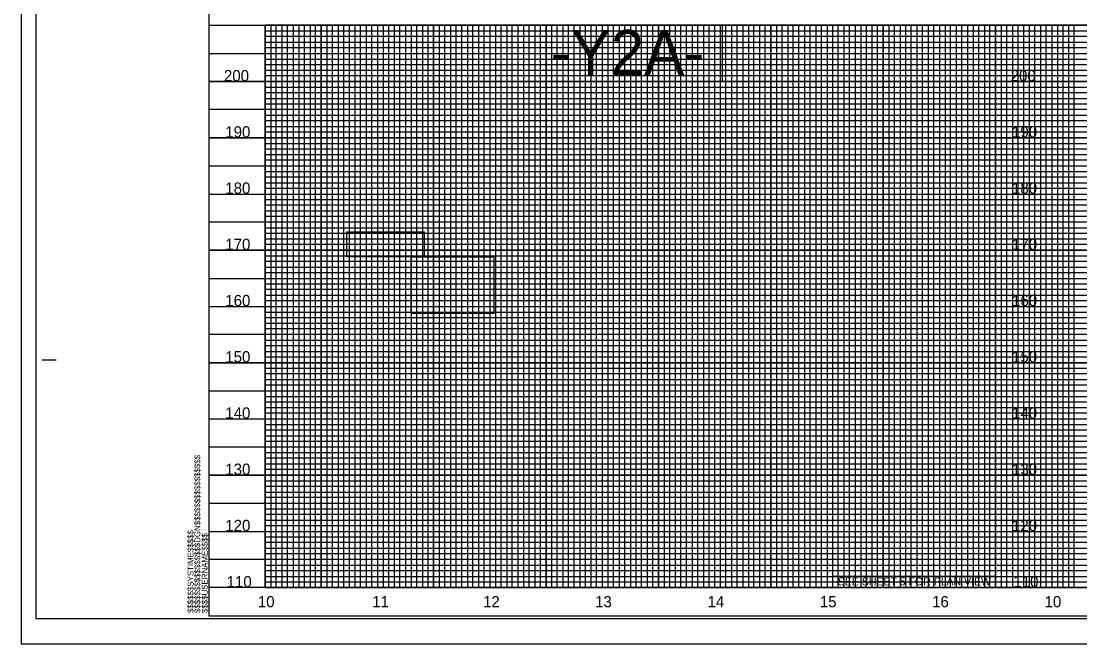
# Model space of a CAD drawing. Extents: x 1779926 to 1781626, y 618464 to 619564.
# Drawn here: x 1779926 to 1780868, y 618464 to 619018 of the extents above; entities that cross this region are included whole.
import ezdxf

# ---------------------------------------------------------------- set-up
doc = ezdxf.new("R2010")
doc.units = 0
for name, color, linetype in [('Exist Vertical Profile Horizontal Axis Label Major', 7, 'Continuous'), ('Exist Vertical Profile Vertical Axis Label', 7, 'Continuous'), ('Prop DSN Text', 7, 'Continuous'), ('Prop Grid Mask', 7, 'Continuous'), ('Sheet DOT Grid CELL', 7, 'Continuous'), ('Sheet Layout Profile Border Port 2', 7, 'Continuous'), ('Sheet Plot Border Inside CELL', 7, 'Continuous'), ('Sheet Plot Border Outside CELL', 7, 'Continuous'), ('Sheet Profile CELL', 7, 'Continuous'), ('Sheet Profile Grid Major CELL', 7, 'Continuous'), ('Sheet Profile Grid Middle CELL', 7, 'Continuous'), ('Sheet Profile Grid Minor CELL', 7, 'Continuous')]:
    doc.layers.add(name, color=color, linetype=linetype)

msp = doc.modelspace()

# ---------------------------------------------------------------- linework, layer by layer
at = {"layer": 'Prop Grid Mask'}
for points in [[(1780550.05, 619014.19), (1780393.09, 619014.19), (1780393.09, 618964.19), (1780550.05, 618964.19)], [(1780792.96, 619014.19), (1780842.96, 619014.19), (1780842.96, 618514.19), (1780792.96, 618514.19)], [(1780215.65, 618830.56), (1780284.61, 618830.56), (1780284.61, 618808.4), (1780215.65, 618808.4)], [(1780272.96, 618808.4), (1780346.37, 618808.4), (1780346.37, 618758.05), (1780272.96, 618758.05)], [(1780792.96, 618524.19), (1780647.96, 618524.19), (1780647.96, 618514.19), (1780792.96, 618514.19)]]:
    msp.add_lwpolyline(points, close=True, dxfattribs=at)
at = {"layer": 'Sheet DOT Grid CELL'}
for p, q in [((1780092.96, 619014.19), (1781592.85, 619014.19)), ((1780142.96, 619014.19), (1780142.96, 618514.19)), ((1780192.96, 619014.19), (1780192.96, 618514.19)), ((1780242.96, 619014.19), (1780242.96, 618514.19)), ((1780292.96, 619014.19), (1780292.96, 618514.19)), ((1780342.96, 619014.19), (1780342.96, 618514.19)), ((1780392.96, 619014.19), (1780392.96, 618514.19)), ((1780442.96, 619014.19), (1780442.96, 618514.19)), ((1780492.96, 619014.19), (1780492.96, 618514.19)), ((1780542.96, 619014.19), (1780542.96, 618514.19)), ((1780592.96, 619014.19), (1780592.96, 618514.19)), ((1780642.96, 619014.19), (1780642.96, 618514.19)), ((1780692.96, 619014.19), (1780692.96, 618514.19)), ((1780742.96, 619014.19), (1780742.96, 618514.19)), ((1780792.96, 619014.19), (1780792.96, 618514.19)), ((1780842.96, 619014.19), (1780842.96, 618514.19)), ((1780092.96, 618964.19), (1781592.85, 618964.19)), ((1780092.96, 618914.19), (1781592.85, 618914.19)), ((1780092.96, 618864.19), (1781592.85, 618864.19)), ((1780092.96, 618814.19), (1781592.85, 618814.19)), ((1780092.96, 618764.19), (1781592.85, 618764.19)), ((1780092.96, 618714.19), (1781592.85, 618714.19)), ((1780092.96, 618664.19), (1781592.85, 618664.19)), ((1780092.96, 618614.19), (1781592.85, 618614.19)), ((1780092.96, 618564.19), (1781592.85, 618564.19))]:
    msp.add_line(p, q, dxfattribs=at)
at = {"layer": 'Sheet Layout Profile Border Port 2'}
msp.add_lwpolyline([(1780142.96, 619014.19), (1781542.96, 619014.19), (1781542.96, 618514.19), (1780142.96, 618514.19)], close=True, dxfattribs=at)
msp.add_lwpolyline([(1781442.96, 619014.19), (1780142.96, 619014.19), (1780142.96, 618514.19), (1781542.96, 618514.19), (1781542.96, 619014.19)], dxfattribs=at)
at = {"layer": 'Sheet Plot Border Inside CELL'}
msp.add_lwpolyline([(1779938.96, 618486.64), (1781605.46, 618486.64), (1781605.46, 619541.74), (1779938.96, 619541.74)], close=True, dxfattribs=at)
at = {"layer": 'Sheet Plot Border Outside CELL'}
msp.add_lwpolyline([(1779925.96, 618464.19), (1781625.96, 618464.19), (1781625.96, 619564.19), (1779925.96, 619564.19)], close=True, dxfattribs=at)
at = {"layer": 'Sheet Profile CELL'}
for p, q in [((1780092.96, 619014.19), (1781592.96, 619014.19)), ((1779944.46, 618716.69), (1779956.96, 618716.69)), ((1781592.96, 618514.19), (1780092.96, 618514.19)), ((1780092.96, 618489.19), (1781592.96, 618489.19)), ((1780092.96, 618489.19), (1780092.96, 618489.19)), ((1780092.96, 618489.19), (1780092.96, 618489.19)), ((1780092.96, 618489.19), (1780092.96, 618489.19)), ((1780092.96, 618489.19), (1780092.96, 618489.19)), ((1780092.96, 618489.19), (1780092.96, 618489.19)), ((1780092.96, 618489.19), (1780092.96, 618489.19)), ((1780092.96, 618489.19), (1780092.96, 618489.19))]:
    msp.add_line(p, q, dxfattribs=at)
msp.add_lwpolyline([(1781592.96, 619539.19), (1780092.96, 619539.19), (1780092.96, 618489.19), (1781592.96, 618489.19)], close=True, dxfattribs=at)
msp.add_lwpolyline([(1780130.46, 618489.19), (1780130.46, 618489.19)], dxfattribs=at)
at = {"layer": 'Sheet Profile Grid Major CELL'}
for p, q in [((1780592.96, 619014.19), (1780642.96, 619014.19)), ((1780692.96, 619014.19), (1780742.96, 619014.19)), ((1780792.96, 619014.19), (1780842.96, 619014.19)), ((1780092.96, 618514.19), (1780092.96, 618514.19))]:
    msp.add_line(p, q, dxfattribs=at)
for points in [[(1780142.96, 619014.19), (1780142.96, 618514.19), (1780192.96, 618514.19), (1780192.96, 619014.19), (1780242.96, 619014.19), (1780242.96, 618514.19), (1780292.96, 618514.19), (1780292.96, 619014.19), (1780342.96, 619014.19), (1780342.96, 618514.19), (1780392.96, 618514.19), (1780392.96, 619014.19), (1780442.96, 619014.19), (1780442.96, 618514.19), (1780492.96, 618514.19), (1780492.96, 619014.19), (1780542.96, 619014.19), (1780542.96, 618514.19), (1780592.96, 618514.19), (1780592.96, 619014.19), (1780642.96, 619014.19), (1780642.96, 618514.19), (1780692.96, 618514.19), (1780692.96, 619014.19), (1780742.96, 619014.19), (1780742.96, 618514.19), (1780792.96, 618514.19), (1780792.96, 619014.19), (1780842.96, 619014.19), (1780842.96, 618514.19), (1780892.96, 618514.19)], [(1781592.96, 618964.19), (1780092.96, 618964.19)], [(1781592.96, 618914.19), (1780092.96, 618914.19), (1780092.96, 618864.19), (1781592.96, 618864.19)], [(1781592.96, 618814.19), (1780092.96, 618814.19), (1780092.96, 618764.19), (1781592.96, 618764.19)], [(1781592.96, 618714.19), (1780092.96, 618714.19), (1780092.96, 618664.19), (1781592.96, 618664.19)], [(1781592.96, 618614.19), (1780092.96, 618614.19), (1780092.96, 618614.19), (1780092.96, 618564.19), (1781592.96, 618564.19)], [(1781592.96, 618514.19), (1780092.96, 618514.19)]]:
    msp.add_lwpolyline(points, dxfattribs=at)
at = {"layer": 'Sheet Profile Grid Middle CELL'}
for points in [[(1780117.96, 619014.19), (1780167.96, 619014.19), (1780167.96, 618514.19), (1780217.96, 618514.19), (1780217.96, 619014.19), (1780267.96, 619014.19), (1780267.96, 618514.19), (1780317.96, 618514.19), (1780317.96, 619014.19), (1780367.96, 619014.19), (1780367.96, 618514.19), (1780417.96, 618514.19), (1780417.96, 619014.19), (1780467.96, 619014.19), (1780467.96, 618514.19), (1780517.96, 618514.19), (1780517.96, 619014.19), (1780567.96, 619014.19), (1780567.96, 618514.19), (1780617.96, 618514.19), (1780617.96, 619014.19), (1780667.96, 619014.19), (1780667.96, 618514.19), (1780717.96, 618514.19), (1780717.96, 618514.19), (1780717.96, 619014.19), (1780767.96, 619014.19), (1780767.96, 618514.19), (1780817.96, 618514.19), (1780817.96, 619014.19), (1780867.96, 619014.19)], [(1780092.96, 618989.19), (1781592.96, 618989.19)], [(1781592.96, 618939.19), (1780092.96, 618939.19), (1780092.96, 618889.19), (1781592.96, 618889.19)], [(1781592.96, 618839.19), (1780092.96, 618839.19), (1780092.96, 618789.19), (1781592.96, 618789.19)], [(1781592.96, 618739.19), (1780092.96, 618739.19), (1780092.96, 618689.19), (1781592.96, 618689.19)], [(1781592.96, 618639.19), (1780092.96, 618639.19), (1780092.96, 618589.19), (1781592.96, 618589.19)], [(1781592.96, 618539.19), (1780092.96, 618539.19)]]:
    msp.add_lwpolyline(points, dxfattribs=at)
at = {"layer": 'Sheet Profile Grid Minor CELL'}
for p, q in [((1780142.96, 619009.19), (1781542.96, 619009.19)), ((1781542.96, 619004.19), (1780142.96, 619004.19)), ((1780142.96, 618999.19), (1781542.96, 618999.19)), ((1781542.96, 618994.19), (1780142.96, 618994.19)), ((1780142.96, 618984.19), (1781542.96, 618984.19)), ((1781542.96, 618979.19), (1780142.96, 618979.19)), ((1780142.96, 618974.19), (1781542.96, 618974.19)), ((1781542.96, 618969.19), (1780142.96, 618969.19)), ((1780142.96, 618959.19), (1781542.96, 618959.19)), ((1781542.96, 618954.19), (1780142.96, 618954.19)), ((1780142.96, 618949.19), (1781542.96, 618949.19)), ((1781542.96, 618944.19), (1780142.96, 618944.19)), ((1780142.96, 618934.19), (1781542.96, 618934.19)), ((1781542.96, 618929.19), (1780142.96, 618929.19)), ((1780142.96, 618924.19), (1781542.96, 618924.19)), ((1781542.96, 618919.19), (1780142.96, 618919.19)), ((1780142.96, 618909.19), (1781542.96, 618909.19)), ((1781542.96, 618904.19), (1780142.96, 618904.19)), ((1780142.96, 618899.19), (1781542.96, 618899.19)), ((1781542.96, 618894.19), (1780142.96, 618894.19)), ((1780142.96, 618884.19), (1781542.96, 618884.19)), ((1781542.96, 618879.19), (1780142.96, 618879.19)), ((1780142.96, 618874.19), (1781542.96, 618874.19)), ((1781542.96, 618869.19), (1780142.96, 618869.19)), ((1780142.96, 618859.19), (1781542.96, 618859.19)), ((1781542.96, 618854.19), (1780142.96, 618854.19)), ((1780142.96, 618849.19), (1781542.96, 618849.19)), ((1781542.96, 618844.19), (1780142.96, 618844.19)), ((1780142.96, 618834.19), (1781542.96, 618834.19)), ((1781542.96, 618829.19), (1780142.96, 618829.19)), ((1780142.96, 618824.19), (1781542.96, 618824.19)), ((1781542.96, 618819.19), (1780142.96, 618819.34)), ((1780142.96, 618809.19), (1781542.96, 618809.19)), ((1781542.96, 618804.19), (1780142.96, 618804.19)), ((1780142.96, 618799.19), (1781542.96, 618799.19)), ((1781542.96, 618794.19), (1780142.96, 618794.19)), ((1780142.96, 618784.19), (1781542.96, 618784.19)), ((1781542.96, 618779.19), (1780142.96, 618779.19)), ((1780142.96, 618774.19), (1781542.96, 618774.19)), ((1781542.96, 618769.19), (1780142.96, 618769.19)), ((1780142.96, 618759.19), (1781542.96, 618759.19)), ((1781542.96, 618754.19), (1780142.96, 618754.19)), ((1780142.96, 618749.19), (1781542.96, 618749.19)), ((1781542.96, 618744.19), (1780142.96, 618744.19)), ((1780142.96, 618734.19), (1781542.96, 618734.19)), ((1781542.96, 618729.19), (1780142.96, 618729.19)), ((1780142.96, 618724.19), (1781542.96, 618724.19)), ((1781542.96, 618719.19), (1780142.96, 618719.19)), ((1780142.96, 618709.19), (1781542.96, 618709.19)), ((1781542.96, 618704.19), (1780142.96, 618704.19)), ((1780142.96, 618699.19), (1781542.96, 618699.19)), ((1781542.96, 618694.19), (1780142.96, 618694.19)), ((1780142.96, 618684.19), (1781542.96, 618684.19)), ((1781542.96, 618679.19), (1780142.96, 618679.19)), ((1780142.96, 618674.19), (1781542.96, 618674.19)), ((1781542.96, 618669.19), (1780142.96, 618669.19)), ((1780142.96, 618659.19), (1781542.96, 618659.19)), ((1781542.96, 618654.19), (1780142.96, 618654.19)), ((1780142.96, 618649.19), (1781542.96, 618649.19)), ((1781542.96, 618644.19), (1780142.96, 618644.19)), ((1780142.96, 618634.19), (1781542.96, 618634.19)), ((1781542.96, 618629.19), (1780142.96, 618629.19)), ((1780142.96, 618624.19), (1781542.96, 618624.19)), ((1781542.96, 618619.19), (1780142.96, 618619.19)), ((1780142.96, 618609.19), (1781542.96, 618609.19)), ((1781542.96, 618604.19), (1780142.96, 618604.19)), ((1780142.96, 618599.19), (1781542.96, 618599.19)), ((1781542.96, 618594.19), (1780142.96, 618594.19)), ((1780142.96, 618584.19), (1781542.96, 618584.19)), ((1781542.96, 618579.19), (1780142.96, 618579.19)), ((1780142.96, 618574.19), (1781542.96, 618574.19)), ((1781542.96, 618569.19), (1780142.96, 618569.19)), ((1780142.96, 618559.19), (1781542.96, 618559.19)), ((1781542.96, 618554.19), (1780142.96, 618554.19)), ((1780142.96, 618549.19), (1781542.96, 618549.19)), ((1781542.96, 618544.19), (1780142.96, 618544.19)), ((1780142.96, 618534.19), (1781542.96, 618534.19)), ((1781542.96, 618529.19), (1780142.96, 618529.19)), ((1780142.96, 618524.19), (1781542.96, 618524.19)), ((1780142.96, 618519.19), (1781542.96, 618519.19))]:
    msp.add_line(p, q, dxfattribs=at)
for points in [[(1780142.96, 619014.19), (1780147.96, 619014.19), (1780147.96, 618514.19), (1780152.96, 618514.19), (1780152.96, 619014.19), (1780157.96, 619014.19), (1780157.96, 618514.19), (1780162.96, 618514.19), (1780162.96, 619014.19), (1780172.96, 619014.19), (1780172.96, 618514.19), (1780177.96, 618514.19), (1780177.96, 619014.19), (1780182.96, 619014.19), (1780182.96, 618514.19), (1780187.96, 618514.19), (1780197.96, 618514.19), (1780202.96, 618514.19), (1780202.96, 619014.19), (1780207.96, 619014.19), (1780207.96, 618514.19), (1780212.96, 618514.19), (1780212.96, 619014.19), (1780222.96, 619014.19), (1780222.96, 618514.19), (1780227.96, 618514.19), (1780227.96, 619014.19), (1780232.96, 619014.19), (1780232.96, 618514.19), (1780237.96, 618514.19), (1780237.96, 619014.19), (1780247.96, 619014.19), (1780247.96, 618514.19), (1780252.96, 618514.19), (1780252.96, 619014.19), (1780257.96, 619014.19), (1780257.96, 618514.19), (1780262.96, 618514.19), (1780262.96, 619014.19), (1780272.96, 619014.19), (1780272.96, 618514.19), (1780277.96, 618514.19), (1780277.96, 619014.19), (1780282.96, 619014.19), (1780282.96, 618514.19), (1780287.96, 618514.19), (1780287.96, 619014.19), (1780297.96, 619014.19), (1780297.96, 618514.19), (1780302.96, 618514.19), (1780302.96, 619014.19), (1780307.96, 619014.19), (1780307.96, 618514.19), (1780312.96, 618514.19), (1780312.96, 619014.19), (1780322.96, 619014.19), (1780322.96, 618514.19), (1780327.96, 618514.19), (1780327.96, 619014.19), (1780332.96, 619014.19), (1780332.96, 618514.19), (1780337.96, 618514.19), (1780337.96, 619014.19), (1780347.96, 619014.19), (1780347.96, 618514.19), (1780352.96, 618514.19), (1780352.96, 619014.19), (1780357.96, 619014.19), (1780357.96, 618514.19)], [(1780187.96, 618514.19), (1780187.96, 619014.19), (1780197.96, 619014.19), (1780197.96, 618514.19)], [(1780357.96, 618514.19), (1780362.96, 618514.19), (1780362.96, 619014.19), (1780372.96, 619014.19), (1780372.96, 618514.19), (1780377.96, 618514.19), (1780377.96, 619014.19), (1780382.96, 619014.19), (1780382.96, 618514.19), (1780387.96, 618514.19), (1780387.96, 619014.19), (1780397.96, 619014.19), (1780397.96, 618514.19), (1780402.96, 618514.19), (1780402.96, 619014.19), (1780407.96, 619014.19), (1780407.96, 618514.19), (1780412.96, 618514.19), (1780412.96, 619014.19), (1780422.96, 619014.19), (1780422.96, 618514.19), (1780427.96, 618514.19), (1780427.96, 619014.19), (1780432.96, 619014.19), (1780432.96, 618514.19), (1780437.96, 618514.19), (1780437.96, 619014.19), (1780447.96, 619014.19), (1780447.96, 618514.19), (1780452.96, 618514.19), (1780452.96, 619014.19), (1780457.96, 619014.19), (1780457.96, 618514.19), (1780462.96, 618514.19), (1780462.96, 619014.19), (1780472.96, 619014.19), (1780472.96, 618514.19), (1780477.96, 618514.19), (1780477.96, 619014.19), (1780482.96, 619014.19), (1780482.96, 618514.19), (1780487.96, 618514.19), (1780487.96, 619014.19), (1780497.96, 619014.19), (1780497.96, 618514.19), (1780502.96, 618514.19), (1780502.96, 619014.19), (1780507.96, 619014.19), (1780507.96, 618514.19), (1780512.96, 618514.19), (1780512.96, 619014.19), (1780522.96, 619014.19), (1780522.96, 618514.19), (1780527.96, 618514.19), (1780527.96, 619014.19), (1780532.96, 619014.19), (1780532.96, 618514.19), (1780537.96, 618514.19), (1780537.96, 619014.19), (1780547.96, 619014.19), (1780547.96, 618514.19), (1780552.96, 618514.19), (1780552.96, 619014.19), (1780557.96, 619014.19), (1780557.96, 618514.19), (1780562.96, 618514.19), (1780562.96, 619014.19), (1780572.96, 619014.19), (1780572.96, 618514.19), (1780577.96, 618514.19), (1780577.96, 619014.19), (1780582.96, 619014.19), (1780582.96, 618514.19), (1780587.96, 618514.19), (1780587.96, 619014.19), (1780597.96, 619014.19), (1780597.96, 618514.19), (1780602.96, 618514.19), (1780602.96, 619014.19), (1780607.96, 619014.19), (1780607.96, 618514.19), (1780612.96, 618514.19), (1780612.96, 619014.19), (1780622.96, 619014.19), (1780622.96, 618514.19), (1780627.96, 618514.19), (1780627.96, 619014.19), (1780632.96, 619014.19), (1780632.96, 618514.19), (1780637.96, 618514.19), (1780637.96, 619014.19), (1780647.96, 619014.19), (1780647.96, 618514.19), (1780652.96, 618514.19), (1780652.96, 619014.19), (1780657.96, 619014.19), (1780657.96, 618514.19), (1780662.96, 618514.19), (1780662.96, 619014.19), (1780672.96, 619014.19)], [(1780672.96, 619014.19), (1780672.96, 618514.19), (1780677.96, 618514.19), (1780677.96, 619014.19), (1780682.96, 619014.19), (1780682.96, 618514.19), (1780687.96, 618514.19), (1780687.96, 619014.19), (1780697.96, 619014.19), (1780697.96, 618514.19), (1780702.96, 618514.19), (1780702.96, 619014.19), (1780707.96, 619014.19), (1780707.96, 618514.19), (1780712.96, 618514.19), (1780712.96, 619014.19), (1780722.96, 619014.19), (1780722.96, 618514.19), (1780727.96, 618514.19), (1780727.96, 619014.19), (1780732.96, 619014.19), (1780732.96, 618514.19), (1780737.96, 618514.19), (1780737.96, 619014.19), (1780747.96, 619014.19), (1780747.96, 618514.19), (1780752.96, 618514.19), (1780752.96, 619014.19), (1780757.96, 619014.19), (1780757.96, 618514.19), (1780762.96, 618514.19), (1780762.96, 619014.19), (1780772.96, 619014.19), (1780772.96, 618514.19), (1780777.96, 618514.19), (1780777.96, 619014.19), (1780782.96, 619014.19), (1780782.96, 618514.19), (1780787.96, 618514.19), (1780787.96, 619014.19), (1780797.96, 619014.19), (1780797.96, 618514.19), (1780797.96, 618514.19), (1780802.96, 618514.19), (1780802.96, 619014.19), (1780807.96, 619014.19), (1780807.96, 618514.19), (1780812.96, 618514.19), (1780812.96, 619014.19), (1780822.96, 619014.19), (1780822.96, 618514.19), (1780827.96, 618514.19), (1780827.96, 619014.19), (1780832.96, 619014.19), (1780832.96, 618514.19), (1780837.96, 618514.19), (1780837.96, 619014.19), (1780847.96, 619014.19), (1780847.96, 618514.19), (1780852.96, 618514.19), (1780852.96, 619014.19), (1780857.96, 619014.19), (1780857.96, 618514.19), (1780862.96, 618514.19), (1780862.96, 619014.19), (1780872.96, 619014.19)]]:
    msp.add_lwpolyline(points, dxfattribs=at)

# ---------------------------------------------------------------- texts
at = {"layer": 'Exist Vertical Profile Horizontal Axis Label Major'}
for s, p in [('10', (1780136.54, 618496.69)), ('11', (1780238.38, 618496.69)), ('12', (1780336.93, 618496.69)), ('13', (1780436.61, 618496.69)), ('14', (1780536.66, 618496.69)), ('15', (1780636.59, 618496.69)), ('16', (1780736.42, 618496.69)), ('10', (1780836.54, 618496.69))]:
    msp.add_text(s, height=10, dxfattribs=at).set_placement(p)
at = {"layer": 'Exist Vertical Profile Vertical Axis Label'}
for s, p in [('200', (1780106.39, 618964.44)), ('200', (1780806.39, 618964.44)), ('190', (1780107.59, 618914.44)), ('190', (1780807.59, 618914.44)), ('180', (1780107.59, 618864.44)), ('180', (1780807.59, 618864.44)), ('170', (1780107.59, 618814.44)), ('170', (1780807.59, 618814.44)), ('160', (1780107.59, 618764.44)), ('160', (1780807.59, 618764.44)), ('150', (1780107.59, 618714.44)), ('150', (1780807.59, 618714.44)), ('140', (1780107.59, 618664.44)), ('140', (1780807.59, 618664.44)), ('130', (1780107.59, 618614.44)), ('130', (1780807.59, 618614.44)), ('120', (1780107.59, 618564.44)), ('120', (1780807.59, 618564.44)), ('110', (1780108.79, 618514.44)), ('110', (1780808.79, 618514.44))]:
    msp.add_text(s, height=10, dxfattribs=at).set_placement(p)
at = {"layer": 'Prop DSN Text'}
for s, height, p in [('-Y2A-', 40, (1780397.01, 618970.14)), ('SEE SHEET 5 FOR PLAN VIEW', 7, (1780652.54, 618516.14))]:
    msp.add_text(s, height=height, dxfattribs=at).set_placement(p)
at = {"layer": 'Sheet Profile CELL'}
for s, p in [('$$$$$$$$$$$$$$$$DGN$$$$$$$$$$$$$$$$', (1780085.32, 618491.57)), ('$$$$$$SYSTIME$$$$$', (1780079.27, 618491.57)), ('$$$$USERNAME$$$$', (1780091.9, 618491.58))]:
    msp.add_text(s, height=5.25, rotation=90, dxfattribs=at).set_placement(p)

doc.saveas('drawing.dxf')
